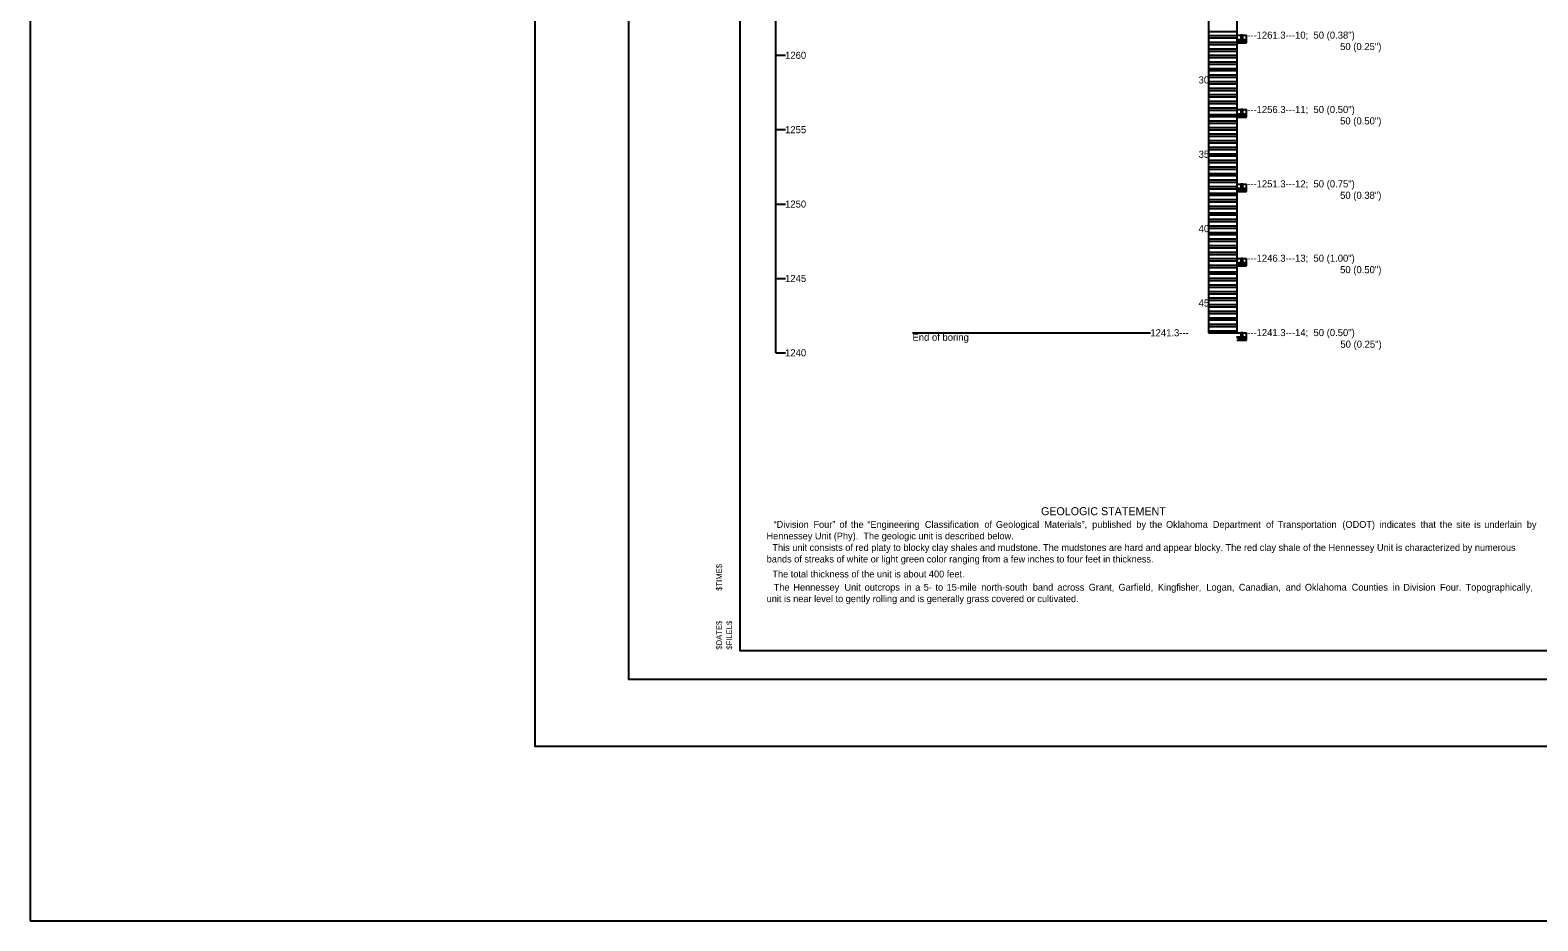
# Model space of a CAD drawing. Extents: x -2 to 138, y 24 to 58.
# Drawn here: x -2.21 to 24.17, y 26.92 to 42.52 of the extents above; entities that cross this region are included whole.
import ezdxf

# ---------------------------------------------------------------- set-up
doc = ezdxf.new("R2010")
doc.units = 0
for name, color, linetype in [('S', 7, 'Continuous'), ('SHT_Plot_Shape_Full', 7, 'Continuous'), ('SHT_Plot_Shape_Half', 7, 'Continuous'), ('SHT_Plot_Stamp', 7, 'Continuous'), ('SHT_Sheet_Border', 7, 'Continuous'), ('Text', 7, 'Continuous')]:
    doc.layers.add(name, color=color, linetype=linetype)

# ---------------------------------------------------------------- blocks, each defined once
blk = doc.blocks.new('Stamp_Plot_Stamp')
at = {"layer": 'SHT_Plot_Stamp'}
for s, p in [('$TIME$', (1.695, 1.572)), ('$DATE$', (1.695, 0.542)), ('$FILEL$', (1.873, 0.542))]:
    blk.add_text(s, height=0.1, rotation=90, dxfattribs=at).set_placement(p)

msp = doc.modelspace()

# ---------------------------------------------------------------- linework, layer by layer
msp.add_line((10.836, 36.866), (10.836, 49.887))
for points in [[(18.405, 49.456), (18.405, 37.217)], [(18.905, 49.456), (18.905, 37.217)], [(18.405, 42.494), (18.905, 42.494)], [(18.405, 42.419), (18.905, 42.419)], [(18.405, 42.38), (18.905, 42.38)], [(18.405, 42.304), (18.905, 42.304)], [(18.405, 42.265), (18.905, 42.265)], [(18.905, 42.425), (19.072, 42.425)], [(18.905, 42.295), (19.072, 42.295)], [(19.072, 42.295), (19.072, 42.425)], [(10.836, 42.075), (11.003, 42.075)], [(18.405, 42.189), (18.905, 42.189)], [(18.405, 42.15), (18.905, 42.15)], [(18.405, 42.075), (18.905, 42.075)], [(18.405, 42.035), (18.905, 42.035)], [(18.405, 41.96), (18.905, 41.96)], [(18.405, 41.92), (18.905, 41.92)], [(18.405, 41.845), (18.905, 41.845)], [(18.405, 41.806), (18.905, 41.806)], [(18.405, 41.73), (18.905, 41.73)], [(18.405, 41.691), (18.905, 41.691)], [(18.405, 41.615), (18.905, 41.615)], [(18.405, 41.576), (18.905, 41.576)], [(18.405, 41.5), (18.905, 41.5)], [(18.405, 41.461), (18.905, 41.461)], [(18.405, 41.386), (18.905, 41.386)], [(18.405, 41.346), (18.905, 41.346)], [(18.405, 41.271), (18.905, 41.271)], [(18.405, 41.231), (18.905, 41.231)], [(18.405, 41.156), (18.905, 41.156)], [(18.405, 41.117), (18.905, 41.117)], [(18.405, 41.041), (18.905, 41.041)], [(18.405, 41.002), (18.905, 41.002)], [(18.405, 40.926), (18.905, 40.926)], [(18.905, 41.123), (19.072, 41.123)], [(18.905, 40.993), (19.072, 40.993)], [(19.072, 40.993), (19.072, 41.123)], [(10.836, 40.773), (11.003, 40.773)], [(18.405, 40.887), (18.905, 40.887)], [(18.405, 40.811), (18.905, 40.811)], [(18.405, 40.772), (18.905, 40.772)], [(18.405, 40.697), (18.905, 40.697)], [(18.405, 40.657), (18.905, 40.657)], [(18.405, 40.582), (18.905, 40.582)], [(18.405, 40.542), (18.905, 40.542)], [(18.405, 40.467), (18.905, 40.467)], [(18.405, 40.428), (18.905, 40.428)], [(18.405, 40.352), (18.905, 40.352)], [(18.405, 40.313), (18.905, 40.313)], [(18.405, 40.237), (18.905, 40.237)], [(18.405, 40.198), (18.905, 40.198)], [(18.405, 40.122), (18.905, 40.122)], [(18.405, 40.083), (18.905, 40.083)], [(18.405, 40.008), (18.905, 40.008)], [(18.405, 39.968), (18.905, 39.968)], [(18.405, 39.893), (18.905, 39.893)], [(18.405, 39.853), (18.905, 39.853)], [(18.405, 39.778), (18.905, 39.778)], [(18.405, 39.739), (18.905, 39.739)], [(18.405, 39.663), (18.905, 39.663)], [(18.405, 39.624), (18.905, 39.624)], [(18.905, 39.821), (19.072, 39.821)], [(18.905, 39.691), (19.072, 39.691)], [(19.072, 39.691), (19.072, 39.821)], [(10.836, 39.47), (11.003, 39.47)], [(18.405, 39.548), (18.905, 39.548)], [(18.405, 39.509), (18.905, 39.509)], [(18.405, 39.433), (18.905, 39.433)], [(18.405, 39.394), (18.905, 39.394)], [(18.405, 39.319), (18.905, 39.319)], [(18.405, 39.279), (18.905, 39.279)], [(18.405, 39.204), (18.905, 39.204)], [(18.405, 39.164), (18.905, 39.164)], [(18.405, 39.089), (18.905, 39.089)], [(18.405, 39.05), (18.905, 39.05)], [(18.405, 38.974), (18.905, 38.974)], [(18.405, 38.935), (18.905, 38.935)], [(18.405, 38.859), (18.905, 38.859)], [(18.405, 38.82), (18.905, 38.82)], [(18.405, 38.744), (18.905, 38.744)], [(18.405, 38.705), (18.905, 38.705)], [(18.405, 38.63), (18.905, 38.63)], [(18.405, 38.59), (18.905, 38.59)], [(18.905, 38.519), (19.072, 38.519)], [(19.072, 38.389), (19.072, 38.519)], [(18.405, 38.515), (18.905, 38.515)], [(18.405, 38.475), (18.905, 38.475)], [(18.405, 38.4), (18.905, 38.4)], [(18.405, 38.361), (18.905, 38.361)], [(18.405, 38.285), (18.905, 38.285)], [(18.905, 38.389), (19.072, 38.389)], [(10.836, 38.168), (11.003, 38.168)], [(18.405, 38.246), (18.905, 38.246)], [(18.405, 38.17), (18.905, 38.17)], [(18.405, 38.131), (18.905, 38.131)], [(18.405, 38.056), (18.905, 38.056)], [(18.405, 38.016), (18.905, 38.016)], [(18.405, 37.941), (18.905, 37.941)], [(18.405, 37.901), (18.905, 37.901)], [(18.405, 37.826), (18.905, 37.826)], [(18.405, 37.786), (18.905, 37.786)], [(18.405, 37.711), (18.905, 37.711)], [(18.405, 37.672), (18.905, 37.672)], [(18.405, 37.596), (18.905, 37.596)], [(18.405, 37.557), (18.905, 37.557)], [(18.405, 37.481), (18.905, 37.481)], [(13.227, 37.217), (17.394, 37.217)], [(18.405, 37.442), (18.905, 37.442)], [(18.405, 37.367), (18.905, 37.367)], [(18.405, 37.327), (18.905, 37.327)], [(18.405, 37.252), (18.905, 37.252)], [(18.405, 37.217), (18.905, 37.217)], [(18.905, 37.217), (19.072, 37.217)], [(19.072, 37.087), (19.072, 37.217)], [(18.905, 37.087), (19.072, 37.087)], [(10.836, 36.866), (11.003, 36.866)]]:
    msp.add_lwpolyline(points)
for points in [[(18.972, 42.347), (18.905, 42.347), (18.988, 42.295), (18.972, 42.347)], [(18.972, 42.347), (19.005, 42.347), (19.005, 42.425), (18.972, 42.347)], [(18.972, 42.347), (19.005, 42.425), (18.972, 42.425), (18.972, 42.347)], [(18.972, 42.347), (18.988, 42.295), (19.005, 42.347), (18.972, 42.347)], [(18.988, 42.295), (19.072, 42.347), (19.005, 42.347), (18.988, 42.295)], [(18.972, 41.045), (18.905, 41.045), (18.988, 40.993), (18.972, 41.045)], [(18.972, 41.045), (19.005, 41.045), (19.005, 41.123), (18.972, 41.045)], [(18.972, 41.045), (19.005, 41.123), (18.972, 41.123), (18.972, 41.045)], [(18.972, 41.045), (18.988, 40.993), (19.005, 41.045), (18.972, 41.045)], [(18.988, 40.993), (19.072, 41.045), (19.005, 41.045), (18.988, 40.993)], [(18.972, 39.743), (18.905, 39.743), (18.988, 39.691), (18.972, 39.743)], [(18.972, 39.743), (19.005, 39.743), (19.005, 39.821), (18.972, 39.743)], [(18.972, 39.743), (19.005, 39.821), (18.972, 39.821), (18.972, 39.743)], [(18.972, 39.743), (18.988, 39.691), (19.005, 39.743), (18.972, 39.743)], [(18.988, 39.691), (19.072, 39.743), (19.005, 39.743), (18.988, 39.691)], [(18.972, 38.441), (19.005, 38.441), (19.005, 38.519), (18.972, 38.441)], [(18.972, 38.441), (19.005, 38.519), (18.972, 38.519), (18.972, 38.441)], [(18.972, 38.441), (18.905, 38.441), (18.988, 38.389), (18.972, 38.441)], [(18.972, 38.441), (18.988, 38.389), (19.005, 38.441), (18.972, 38.441)], [(18.988, 38.389), (19.072, 38.441), (19.005, 38.441), (18.988, 38.389)], [(18.972, 37.139), (19.005, 37.139), (19.005, 37.217), (18.972, 37.139)], [(18.972, 37.139), (19.005, 37.217), (18.972, 37.217), (18.972, 37.139)], [(18.972, 37.139), (18.905, 37.139), (18.988, 37.087), (18.972, 37.139)], [(18.972, 37.139), (18.988, 37.087), (19.005, 37.139), (18.972, 37.139)], [(18.988, 37.087), (19.072, 37.139), (19.005, 37.139), (18.988, 37.087)]]:
    msp.add_lwpolyline(points, close=True)
at = {"layer": 'S'}
msp.add_lwpolyline([(-2.212, 26.92), (137.529, 26.92), (137.529, 58.049), (-2.212, 58.049)], close=True, dxfattribs=at)
at = {"layer": 'SHT_Plot_Shape_Full'}
msp.add_lwpolyline([(6.624, 53.971), (42.624, 53.971), (42.624, 29.971), (6.624, 29.971)], close=True, dxfattribs=at)
at = {"layer": 'SHT_Plot_Shape_Half'}
msp.add_lwpolyline([(8.262, 53.146), (42.262, 53.146), (42.262, 31.146), (8.262, 31.146)], close=True, dxfattribs=at)
at = {"layer": 'SHT_Sheet_Border'}
msp.add_lwpolyline([(10.212, 52.646), (41.712, 52.646), (41.712, 31.646), (10.212, 31.646)], close=True, dxfattribs=at)

# ---------------------------------------------------------------- block references
at = {"layer": 'SHT_Plot_Stamp'}
msp.add_blockref('Stamp_Plot_Stamp', (8.198, 31.127), dxfattribs=at)

# ---------------------------------------------------------------- texts
for s, p in [('---1261.3---10;  50 (0.38")', (19.083, 42.366)), ('50 (0.25")', (20.71, 42.166)), ('1260', (10.998, 42.013)), ('30', (18.234, 41.582)), ('---1256.3---11;  50 (0.50")', (19.083, 41.064)), ('50 (0.50")', (20.71, 40.864)), ('1255', (10.998, 40.711)), ('35', (18.234, 40.28)), ('---1251.3---12;  50 (0.75")', (19.083, 39.762)), ('50 (0.38")', (20.71, 39.562)), ('1250', (10.998, 39.408)), ('40', (18.234, 38.978)), ('---1246.3---13;  50 (1.00")', (19.083, 38.46)), ('50 (0.50")', (20.71, 38.26)), ('1245', (10.998, 38.106)), ('45', (18.234, 37.676)), ('End of boring', (13.227, 37.076)), ('1241.3---', (17.389, 37.155)), ('---1241.3---14;  50 (0.50")', (19.083, 37.158)), ('50 (0.25")', (20.715, 36.954)), ('1240', (10.998, 36.804))]:
    msp.add_text(s, height=0.124).set_placement(p)
at = {"layer": 'Text'}
for s, height, p in [('GEOLOGIC STATEMENT', 0.14, (15.476, 34.023)), ('“Division', 0.12, (10.797, 33.801)), ('Four”', 0.12, (11.494, 33.801)), ('of', 0.12, (11.95, 33.801)), ('the', 0.12, (12.15, 33.801)), ('“Engineering', 0.12, (12.438, 33.801)), ('Classification', 0.12, (13.444, 33.801)), ('of', 0.12, (14.486, 33.801)), ('Geological', 0.12, (14.687, 33.801)), ('Materials”,', 0.12, (15.534, 33.801)), ('published', 0.12, (16.371, 33.801)), ('by', 0.12, (17.144, 33.801)), ('the', 0.12, (17.376, 33.801)), ('Oklahoma', 0.12, (17.664, 33.801)), ('Department', 0.12, (18.483, 33.801)), ('of', 0.12, (19.414, 33.801)), ('Transportation', 0.12, (19.614, 33.801)), ('(ODOT)', 0.12, (20.75, 33.801)), ('indicates', 0.12, (21.401, 33.801)), ('that', 0.12, (22.118, 33.801)), ('the', 0.12, (22.452, 33.801)), ('site', 0.12, (22.74, 33.801)), ('is', 0.12, (23.056, 33.801)), ('underlain', 0.12, (23.232, 33.801)), ('by', 0.12, (23.977, 33.801)), ('Hennessey Unit (Phy).  The geologic unit is described below.', 0.12, (10.673, 33.599)), ('  This unit consists of red platy to blocky clay shales and mudstone. The mudstones are hard and appear blocky. The red clay shale of the Hennessey Unit is characterized by numerous ', 0.12, (10.687, 33.397)), ('bands of streaks of white or light green color ranging from a few inches to four feet in thickness.', 0.12, (10.676, 33.195)), ('  The total thickness of the unit is about 400 feet.', 0.12, (10.687, 32.933)), ('The', 0.12, (10.798, 32.701)), ('Hennessey', 0.12, (11.143, 32.701)), ('Unit', 0.12, (12.037, 32.701)), ('outcrops', 0.12, (12.391, 32.701)), ('in', 0.12, (13.089, 32.701)), ('a', 0.12, (13.275, 32.701)), ('5-', 0.12, (13.424, 32.701)), ('to', 0.12, (13.629, 32.701)), ('15-mile', 0.12, (13.824, 32.701)), ('north-south', 0.12, (14.43, 32.701)), ('band', 0.12, (15.333, 32.701)), ('across', 0.12, (15.762, 32.701)), ('Grant,', 0.12, (16.311, 32.701)), ('Garfield,', 0.12, (16.833, 32.701)), ('Kingfisher,', 0.12, (17.522, 32.701)), ('Logan,', 0.12, (18.37, 32.701)), ('Canadian,', 0.12, (18.938, 32.701)), ('and', 0.12, (19.758, 32.701)), ('Oklahoma', 0.12, (20.093, 32.701)), ('Counties', 0.12, (20.913, 32.701)), ('in', 0.12, (21.63, 32.701)), ('Division', 0.12, (21.816, 32.701)), ('Four.', 0.12, (22.459, 32.701)), ('Topographically,', 0.12, (22.906, 32.701)), ('unit is near level to gently rolling and is generally grass covered or cultivated.  ', 0.12, (10.676, 32.501))]:
    msp.add_text(s, height=height, dxfattribs=at).set_placement(p)

doc.saveas('drawing.dxf')
